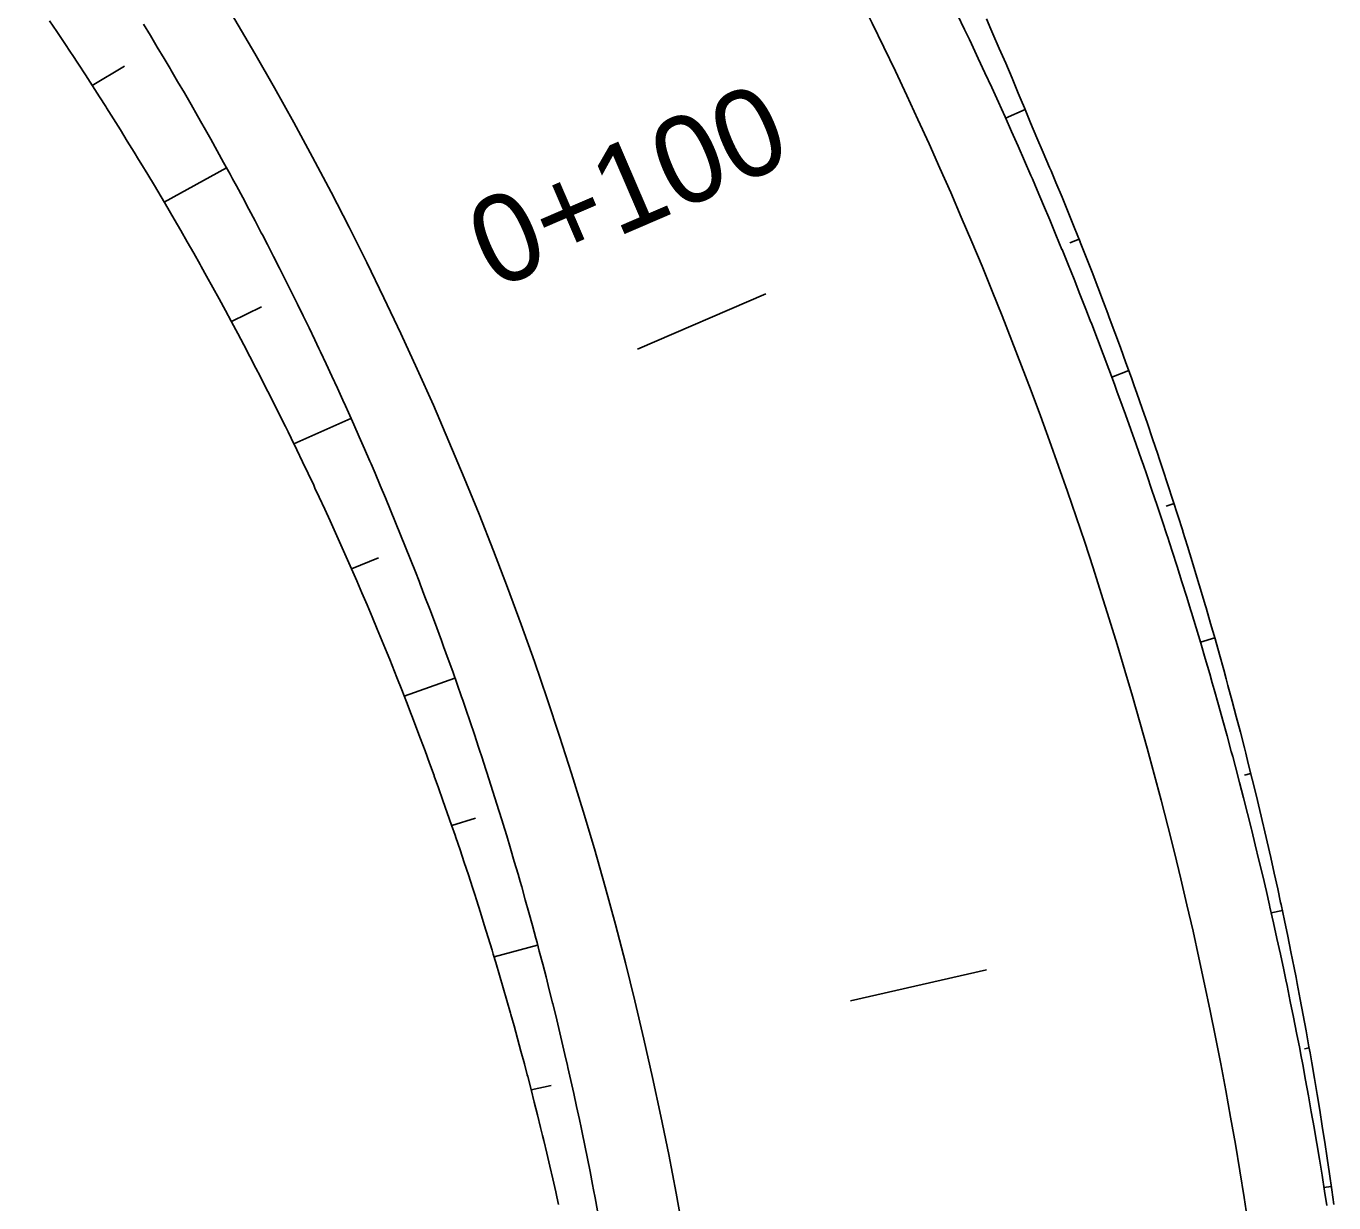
# Model space of a CAD drawing. Extents: x 6503541 to 6503743, y 5888004 to 5888145.
# Drawn here: x 6503702.7333 to 6503703.1822, y 5888105.6053 to 5888106.009 of the extents above; entities that cross this region are included whole.
import ezdxf

# ---------------------------------------------------------------- set-up
doc = ezdxf.new("R2010")
doc.units = 0
doc.layers.add('12', color=7, linetype='Continuous')

msp = doc.modelspace()

# ---------------------------------------------------------------- linework, layer by layer
at = {"layer": '12'}
for points in [[(6503702.91607, 5888105.60465), (6503702.91547, 5888105.60736), (6503702.91508, 5888105.60906), (6503702.91408, 5888105.61347), (6503702.91307, 5888105.61787), (6503702.91203, 5888105.62227), (6503702.91098, 5888105.62667), (6503702.91058, 5888105.62832), (6503702.90991, 5888105.63106), (6503702.90883, 5888105.63544), (6503702.90773, 5888105.63982), (6503702.90661, 5888105.6442), (6503702.90548, 5888105.64857), (6503702.90532, 5888105.64918), (6503702.90433, 5888105.65293), (6503702.90316, 5888105.6573), (6503702.90198, 5888105.66165), (6503702.90078, 5888105.666), (6503702.89968, 5888105.66992), (6503702.89956, 5888105.67035), (6503702.89833, 5888105.67469), (6503702.89708, 5888105.67902), (6503702.89581, 5888105.68335), (6503702.89453, 5888105.68768), (6503702.89367, 5888105.69055), (6503702.89323, 5888105.692), (6503702.89192, 5888105.69631), (6503702.89058, 5888105.70062), (6503702.88924, 5888105.70492), (6503702.88787, 5888105.70922), (6503702.88728, 5888105.71106), (6503702.88649, 5888105.71351), (6503702.8851, 5888105.71779), (6503702.88368, 5888105.72207), (6503702.88225, 5888105.72634), (6503702.88081, 5888105.73061), (6503702.88053, 5888105.73143), (6503702.87935, 5888105.73487), (6503702.87787, 5888105.73913), (6503702.87638, 5888105.74337), (6503702.87487, 5888105.74762), (6503702.87341, 5888105.75166), (6503702.87334, 5888105.75185), (6503702.8718, 5888105.75608), (6503702.87024, 5888105.76031), (6503702.86867, 5888105.76452), (6503702.86708, 5888105.76873), (6503702.86593, 5888105.77175), (6503702.86548, 5888105.77294), (6503702.86386, 5888105.77713), (6503702.86222, 5888105.78132), (6503702.86057, 5888105.78551), (6503702.8589, 5888105.78968), (6503702.85809, 5888105.79169), (6503702.85721, 5888105.79385), (6503702.85551, 5888105.79802), (6503702.8538, 5888105.80217), (6503702.85207, 5888105.80632), (6503702.85032, 5888105.81046), (6503702.84989, 5888105.81147), (6503702.84856, 5888105.8146), (6503702.84678, 5888105.81872), (6503702.84499, 5888105.82284), (6503702.84318, 5888105.82696), (6503702.84135, 5888105.83106), (6503702.84134, 5888105.83109), (6503702.83951, 5888105.83516), (6503702.83766, 5888105.83925), (6503702.83579, 5888105.84333), (6503702.8339, 5888105.84741), (6503702.83244, 5888105.85054), (6503702.832, 5888105.85147), (6503702.83009, 5888105.85553), (6503702.82815, 5888105.85958), (6503702.82621, 5888105.86363), (6503702.82425, 5888105.86766), (6503702.82319, 5888105.86981), (6503702.82227, 5888105.87169), (6503702.82028, 5888105.87571), (6503702.81827, 5888105.87972), (6503702.81625, 5888105.88372), (6503702.81421, 5888105.88772), (6503702.8136, 5888105.8889), (6503702.81216, 5888105.89171), (6503702.81009, 5888105.89568), (6503702.80801, 5888105.89965), (6503702.80591, 5888105.90361), (6503702.8038, 5888105.90757), (6503702.80367, 5888105.9078), (6503702.80167, 5888105.91151), (6503702.79953, 5888105.91545), (6503702.79737, 5888105.91938), (6503702.7952, 5888105.92329), (6503702.79341, 5888105.92651), (6503702.79302, 5888105.9272), (6503702.79082, 5888105.9311), (6503702.7886, 5888105.935), (6503702.78637, 5888105.93888), (6503702.78413, 5888105.94275), (6503702.78281, 5888105.94502), (6503702.78187, 5888105.94662), (6503702.7796, 5888105.95047), (6503702.77731, 5888105.95432), (6503702.77501, 5888105.95816), (6503702.7727, 5888105.96199), (6503702.77189, 5888105.96332), (6503702.77037, 5888105.96581), (6503702.76802, 5888105.96962), (6503702.76566, 5888105.97342), (6503702.76329, 5888105.97721), (6503702.7609, 5888105.98099), (6503702.76064, 5888105.98141), (6503702.7585, 5888105.98476), (6503702.75609, 5888105.98852), (6503702.75366, 5888105.99228), (6503702.75122, 5888105.99602), (6503702.74907, 5888105.99928), (6503702.74876, 5888105.99975), (6503702.74629, 5888106.00347), (6503702.74381, 5888106.00719), (6503702.74131, 5888106.01089)], [(6503703.17979, 5888105.60435), (6503703.17902, 5888105.60932), (6503703.17816, 5888105.61477), (6503703.17727, 5888105.62021), (6503703.17636, 5888105.62564), (6503703.17558, 5888105.63026), (6503703.17544, 5888105.63107), (6503703.17449, 5888105.6365), (6503703.17352, 5888105.64193), (6503703.17253, 5888105.64735), (6503703.17152, 5888105.65276), (6503703.17089, 5888105.65608), (6503703.17049, 5888105.65818), (6503703.16944, 5888105.66359), (6503703.16837, 5888105.66899), (6503703.16728, 5888105.67439), (6503703.16617, 5888105.67979), (6503703.16574, 5888105.68182), (6503703.16503, 5888105.68518), (6503703.16388, 5888105.69057), (6503703.1627, 5888105.69596), (6503703.16151, 5888105.70134), (6503703.16029, 5888105.70671), (6503703.16012, 5888105.70746), (6503703.15906, 5888105.71208), (6503703.1578, 5888105.71745), (6503703.15652, 5888105.72281), (6503703.15523, 5888105.72816), (6503703.15404, 5888105.73299), (6503703.15391, 5888105.73351), (6503703.15257, 5888105.73886), (6503703.15121, 5888105.7442), (6503703.14983, 5888105.74953), (6503703.14843, 5888105.75486), (6503703.14749, 5888105.75841), (6503703.14701, 5888105.76019), (6503703.14557, 5888105.76551), (6503703.14411, 5888105.77082), (6503703.14263, 5888105.77613), (6503703.14113, 5888105.78143), (6503703.14048, 5888105.7837), (6503703.13961, 5888105.78673), (6503703.13807, 5888105.79202), (6503703.13651, 5888105.7973), (6503703.13492, 5888105.80258), (6503703.13332, 5888105.80785), (6503703.13301, 5888105.80886), (6503703.1317, 5888105.81312), (6503703.13006, 5888105.81838), (6503703.1284, 5888105.82363), (6503703.12671, 5888105.82888), (6503703.12509, 5888105.83389), (6503703.12501, 5888105.83412), (6503703.12329, 5888105.83936), (6503703.12155, 5888105.84459), (6503703.11978, 5888105.84981), (6503703.118, 5888105.85502), (6503703.11671, 5888105.85876), (6503703.1162, 5888105.86023), (6503703.11438, 5888105.86543), (6503703.11254, 5888105.87062), (6503703.11068, 5888105.87581), (6503703.10879, 5888105.88099), (6503703.10788, 5888105.88348), (6503703.10689, 5888105.88616), (6503703.10497, 5888105.89133), (6503703.10303, 5888105.89648), (6503703.10107, 5888105.90163), (6503703.09909, 5888105.90678), (6503703.09861, 5888105.90803), (6503703.09709, 5888105.91191), (6503703.09507, 5888105.91704), (6503703.09304, 5888105.92216), (6503703.09098, 5888105.92727), (6503703.0889, 5888105.93237), (6503703.08888, 5888105.93241), (6503703.0868, 5888105.93747), (6503703.08469, 5888105.94256), (6503703.08255, 5888105.94764), (6503703.0804, 5888105.95271), (6503703.07872, 5888105.95661), (6503703.07822, 5888105.95777), (6503703.07603, 5888105.96283), (6503703.07381, 5888105.96788), (6503703.07158, 5888105.97291), (6503703.06933, 5888105.97794), (6503703.06812, 5888105.98062), (6503703.06706, 5888105.98296), (6503703.06477, 5888105.98798), (6503703.06246, 5888105.99298), (6503703.06013, 5888105.99797), (6503703.05778, 5888106.00296), (6503703.05709, 5888106.00444), (6503703.05542, 5888106.00794), (6503703.05303, 5888106.0129)], [(6503703.18222, 5888105.60473), (6503703.18152, 5888105.60972), (6503703.18074, 5888105.61518), (6503703.17993, 5888105.62064), (6503703.1791, 5888105.6261), (6503703.17838, 5888105.63074), (6503703.17825, 5888105.63156), (6503703.17738, 5888105.63701), (6503703.17649, 5888105.64246), (6503703.17557, 5888105.64791), (6503703.17464, 5888105.65335), (6503703.17406, 5888105.65669), (6503703.17368, 5888105.65879), (6503703.17271, 5888105.66423), (6503703.17171, 5888105.66966), (6503703.17069, 5888105.67509), (6503703.16965, 5888105.68052), (6503703.16925, 5888105.68256), (6503703.16858, 5888105.68594), (6503703.1675, 5888105.69136), (6503703.1664, 5888105.69677), (6503703.16527, 5888105.70218), (6503703.16413, 5888105.70759), (6503703.16396, 5888105.70834), (6503703.16296, 5888105.71299), (6503703.16177, 5888105.71838), (6503703.16056, 5888105.72378), (6503703.15933, 5888105.72916), (6503703.1582, 5888105.73402), (6503703.15808, 5888105.73455), (6503703.15681, 5888105.73993), (6503703.15551, 5888105.7453), (6503703.1542, 5888105.75067), (6503703.15286, 5888105.75604), (6503703.15196, 5888105.7596), (6503703.15151, 5888105.7614), (6503703.15013, 5888105.76675), (6503703.14873, 5888105.7721), (6503703.14731, 5888105.77744), (6503703.14587, 5888105.78278), (6503703.14525, 5888105.78507), (6503703.14441, 5888105.78812), (6503703.14293, 5888105.79345), (6503703.14143, 5888105.79877), (6503703.13991, 5888105.80408), (6503703.13836, 5888105.8094), (6503703.13806, 5888105.81041), (6503703.1368, 5888105.8147), (6503703.13521, 5888105.82), (6503703.13361, 5888105.82529), (6503703.13198, 5888105.83058), (6503703.13041, 5888105.83562), (6503703.13033, 5888105.83586), (6503703.12867, 5888105.84114), (6503703.12698, 5888105.84641), (6503703.12527, 5888105.85167), (6503703.12354, 5888105.85693), (6503703.12229, 5888105.8607), (6503703.12179, 5888105.86218), (6503703.12002, 5888105.86742), (6503703.11823, 5888105.87265), (6503703.11642, 5888105.87788), (6503703.11459, 5888105.88311), (6503703.1137, 5888105.88562), (6503703.11274, 5888105.88832), (6503703.11086, 5888105.89353), (6503703.10897, 5888105.89873), (6503703.10706, 5888105.90393), (6503703.10513, 5888105.90911), (6503703.10465, 5888105.91038), (6503703.10317, 5888105.91429), (6503703.1012, 5888105.91947), (6503703.09921, 5888105.92463), (6503703.09719, 5888105.92979), (6503703.09516, 5888105.93494), (6503703.09514, 5888105.93497), (6503703.0931, 5888105.94008), (6503703.09102, 5888105.94521), (6503703.08891, 5888105.95033), (6503703.08679, 5888105.95544), (6503703.08514, 5888105.95937), (6503703.08464, 5888105.96055), (6503703.08248, 5888105.96564), (6503703.0803, 5888105.97073), (6503703.07814, 5888105.97584), (6503703.07603, 5888105.98096), (6503703.07489, 5888105.98369), (6503703.0739, 5888105.98607), (6503703.07174, 5888105.99118), (6503703.06957, 5888105.99628), (6503703.06738, 5888106.00137), (6503703.06516, 5888106.00645), (6503703.0645, 5888106.00796), (6503703.06293, 5888106.01153)], [(6503702.92943, 5888105.60252), (6503702.92859, 5888105.60701), (6503702.92807, 5888105.60976), (6503702.92774, 5888105.6115), (6503702.92687, 5888105.61598), (6503702.92598, 5888105.62046), (6503702.92508, 5888105.62494), (6503702.92415, 5888105.62941), (6503702.9238, 5888105.63109), (6503702.92321, 5888105.63388), (6503702.92226, 5888105.63834), (6503702.92128, 5888105.64281), (6503702.92029, 5888105.64726), (6503702.91929, 5888105.65172), (6503702.91915, 5888105.65234), (6503702.91826, 5888105.65617), (6503702.91722, 5888105.66062), (6503702.91616, 5888105.66506), (6503702.91509, 5888105.6695), (6503702.9141, 5888105.6735), (6503702.91399, 5888105.67393), (6503702.91289, 5888105.67836), (6503702.91176, 5888105.68279), (6503702.91062, 5888105.68721), (6503702.90946, 5888105.69163), (6503702.90868, 5888105.69456), (6503702.90828, 5888105.69604), (6503702.90709, 5888105.70045), (6503702.90588, 5888105.70485), (6503702.90465, 5888105.70925), (6503702.90341, 5888105.71364), (6503702.90287, 5888105.71553), (6503702.90214, 5888105.71803), (6503702.90087, 5888105.72242), (6503702.89957, 5888105.7268), (6503702.89826, 5888105.73117), (6503702.89693, 5888105.73554), (6503702.89668, 5888105.73638), (6503702.89559, 5888105.73991), (6503702.89423, 5888105.74427), (6503702.89285, 5888105.74862), (6503702.89146, 5888105.75297), (6503702.89011, 5888105.75712), (6503702.89005, 5888105.75731), (6503702.88862, 5888105.76165), (6503702.88718, 5888105.76598), (6503702.88572, 5888105.77031), (6503702.88424, 5888105.77463), (6503702.88317, 5888105.77773), (6503702.88274, 5888105.77895), (6503702.88124, 5888105.78326), (6503702.87971, 5888105.78756), (6503702.87817, 5888105.79186), (6503702.87661, 5888105.79615), (6503702.87585, 5888105.79822), (6503702.87503, 5888105.80044), (6503702.87344, 5888105.80472), (6503702.87183, 5888105.809), (6503702.87021, 5888105.81326), (6503702.86857, 5888105.81753), (6503702.86816, 5888105.81857), (6503702.86691, 5888105.82178), (6503702.86524, 5888105.82603), (6503702.86355, 5888105.83027), (6503702.86184, 5888105.83451), (6503702.86012, 5888105.83874), (6503702.86011, 5888105.83877), (6503702.85838, 5888105.84296), (6503702.85663, 5888105.84718), (6503702.85486, 5888105.85139), (6503702.85307, 5888105.85559), (6503702.85168, 5888105.85883), (6503702.85127, 5888105.85979), (6503702.84945, 5888105.86398), (6503702.84762, 5888105.86816), (6503702.84577, 5888105.87234), (6503702.8439, 5888105.87651), (6503702.8429, 5888105.87873), (6503702.84202, 5888105.88067), (6503702.84012, 5888105.88482), (6503702.83821, 5888105.88897), (6503702.83628, 5888105.89311), (6503702.83433, 5888105.89724), (6503702.83375, 5888105.89846), (6503702.83237, 5888105.90136), (6503702.83039, 5888105.90548), (6503702.8284, 5888105.90959), (6503702.82639, 5888105.91369), (6503702.82437, 5888105.91779), (6503702.82425, 5888105.91803), (6503702.82233, 5888105.92187), (6503702.82028, 5888105.92595), (6503702.8182, 5888105.93002), (6503702.81612, 5888105.93408), (6503702.81439, 5888105.93742), (6503702.81402, 5888105.93814), (6503702.8119, 5888105.94218), (6503702.80977, 5888105.94622), (6503702.80762, 5888105.95025), (6503702.80546, 5888105.95428), (6503702.80418, 5888105.95663), (6503702.80328, 5888105.95829), (6503702.80108, 5888105.9623), (6503702.79888, 5888105.96629), (6503702.79665, 5888105.97028), (6503702.79441, 5888105.97426), (6503702.79363, 5888105.97565), (6503702.79216, 5888105.97823), (6503702.78989, 5888105.9822), (6503702.7876, 5888105.98615), (6503702.7853, 5888105.9901), (6503702.78299, 5888105.99403), (6503702.78273, 5888105.99447), (6503702.78066, 5888105.99796), (6503702.77831, 5888106.00188), (6503702.77595, 5888106.00579), (6503702.77358, 5888106.00969)], [(6503702.756, 5888105.98866), (6503702.7671, 5888105.99534)], [(6503703.07624, 5888105.98046), (6503703.06953, 5888105.97744)], [(6503702.78068, 5888105.94865), (6503702.80209, 5888105.96039)], [(6503703.09476, 5888105.93592), (6503703.09162, 5888105.93463)], [(6503702.94316, 5888105.89823), (6503702.98725, 5888105.91721)], [(6503702.80376, 5888105.90764), (6503702.81405, 5888105.91275)], [(6503703.11184, 5888105.89083), (6503703.10596, 5888105.88864)], [(6503702.82521, 5888105.86568), (6503702.84479, 5888105.87444)], [(6503703.12737, 5888105.8452), (6503703.12465, 5888105.84429)], [(6503702.84499, 5888105.82283), (6503702.85426, 5888105.82654)], [(6503703.14134, 5888105.79909), (6503703.13639, 5888105.79761)], [(6503702.86306, 5888105.77917), (6503702.88045, 5888105.78534)], [(6503703.15373, 5888105.75255), (6503703.15153, 5888105.75197)], [(6503702.87938, 5888105.73477), (6503702.8875, 5888105.73728)], [(6503703.16454, 5888105.70563), (6503703.16072, 5888105.70477)], [(6503702.89393, 5888105.68969), (6503702.90888, 5888105.69367)], [(6503703.06303, 5888105.68525), (6503703.01624, 5888105.67455)], [(6503703.17375, 5888105.6584), (6503703.17215, 5888105.65809)], [(6503702.90666, 5888105.644), (6503702.91349, 5888105.64553)], [(6503703.18135, 5888105.6109), (6503703.17881, 5888105.6105)]]:
    msp.add_lwpolyline(points, dxfattribs=at)
for radius, start, end in [(1.416, 322.92795, 58.08457), (1.224, 335.5823, 58.04976)]:
    msp.add_arc((6503701.75287, 5888105.38557), radius, start, end, dxfattribs=at)

# ---------------------------------------------------------------- texts
msp.add_text('0+100', height=0.03, rotation=23.3013, dxfattribs=at).set_placement((6503702.89391, 5888105.91838))

doc.saveas('drawing.dxf')
